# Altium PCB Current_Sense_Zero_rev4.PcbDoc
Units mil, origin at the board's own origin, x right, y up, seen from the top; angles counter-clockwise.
Board outline 2450 x 1350 mil, 2 copper layers (Top Layer, Bottom Layer); 28 components, 9 nets, 61 pads, 43 vias.
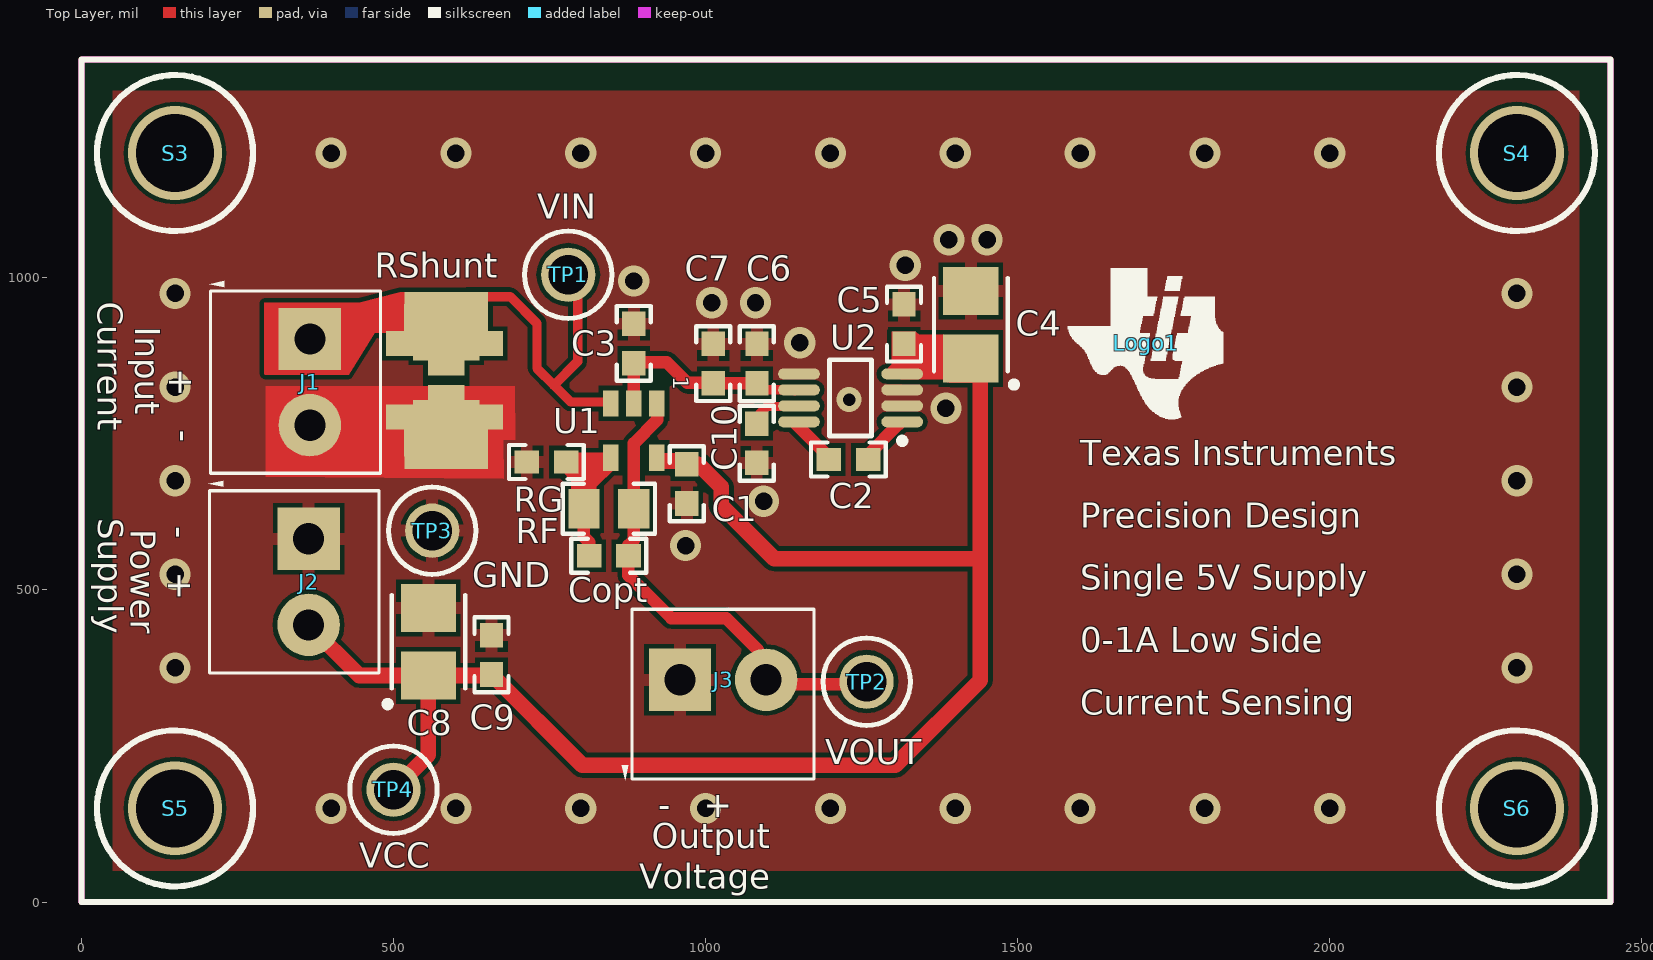
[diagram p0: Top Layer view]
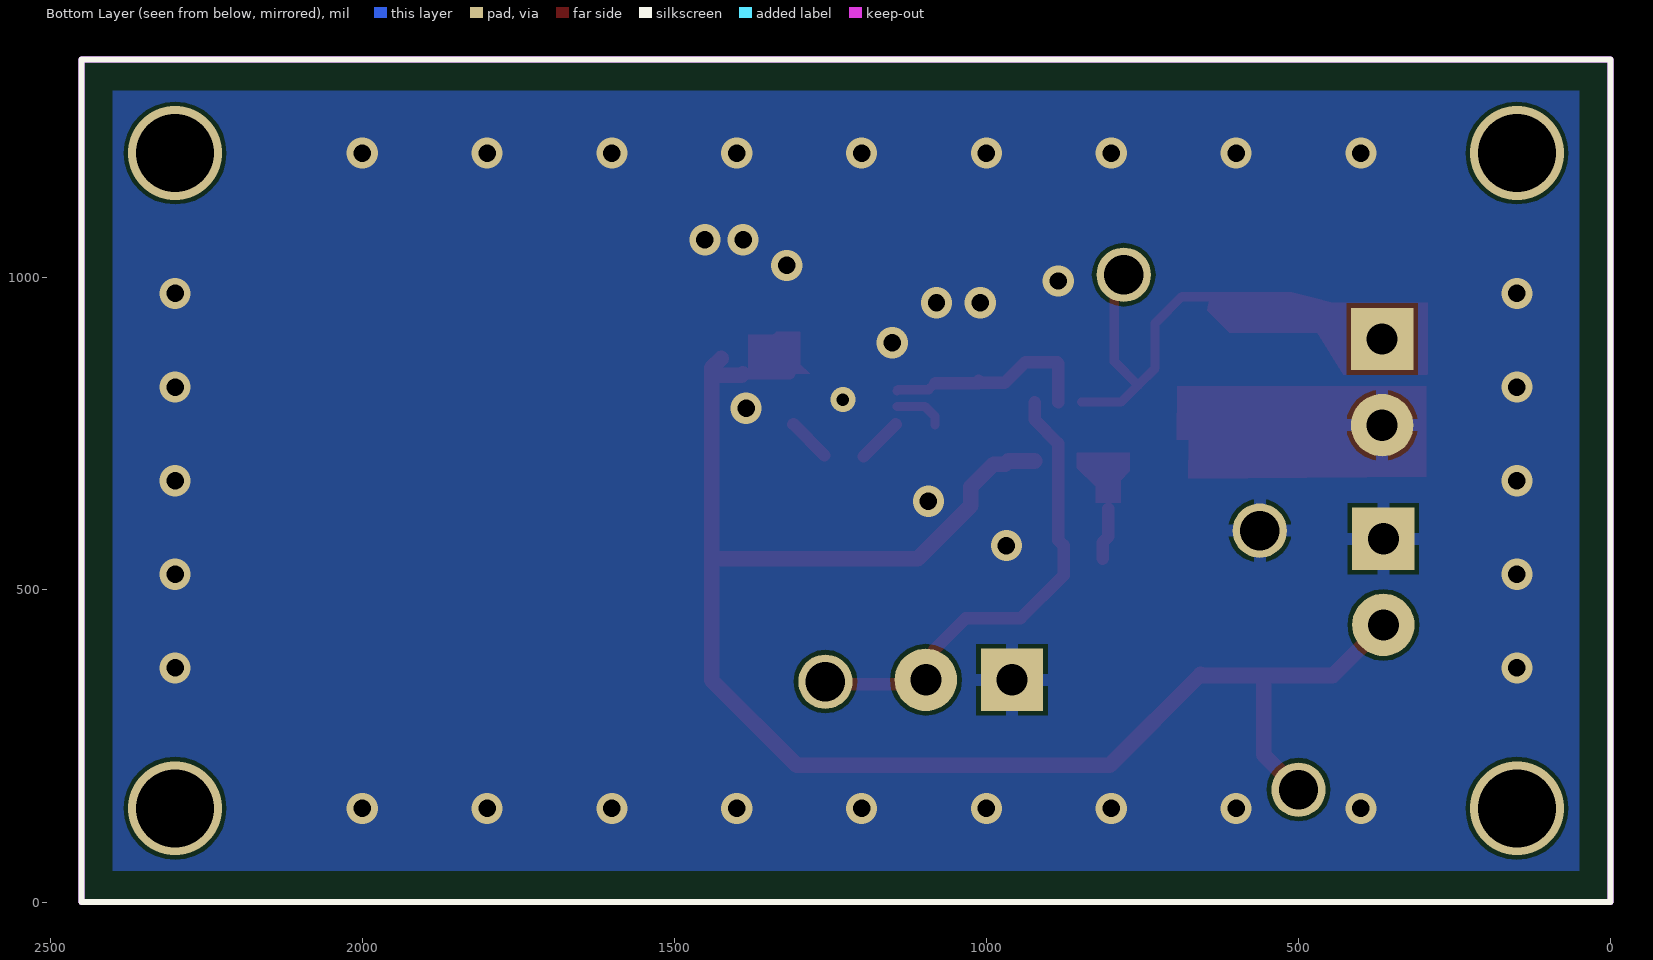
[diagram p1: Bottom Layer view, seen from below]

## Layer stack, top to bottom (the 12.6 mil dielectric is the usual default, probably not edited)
Top Layer: signal copper 1.4
Dielectric: core 12.6, FR-4, Dk 4.8
Bottom Layer: signal copper 1.4

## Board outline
0,0 0,1350 2450,1350 2450,0 0,0

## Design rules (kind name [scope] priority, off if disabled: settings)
AssemblyTestPointUsage [All] p1 off:
AssemblyTestpoint [All] p1 off: testpointundercomponent=TRUE minsize=40 maxsize=100 preferedsize=60 minholesize=0 maxholesize=40 preferedholesize=32 testpointgrid=1 usegrid=TRUE gridtolerance=0.01 allowsidetop=TRUE allowsidebottom=TRUE
Clearance [All] p1: gap=7
ComponentClearance [All] p1 off: gap=10 collisioncheckmode=3 verticalgap=10 showdistances=FALSE
DiffPairsRouting [All] p1 off: maxlimit=10 minlimit=10 mostfreqgap=10 maxuncoupledlength=500
FabricationTestPointUsage TestPointUsage [All] p1 off: valid=0 allowmultiple=FALSE
FabricationTestpoint Testpoint [All] p1 off: side=3 testpointundercomponent=TRUE minsize=40 maxsize=100 preferedsize=60 minholesize=0 maxholesize=40 preferedholesize=32 testpointgrid=1 allowsidetop=TRUE allowsidebottom=TRUE usegrid=TRUE gridtolerance=0.01
FanoutControl Fanout_BGA [IsBGA] p1 off: bgadir=Out bgaviamode=Centered fanoutstyle=Auto fanoutdirection=Alternating viagrid=1 // Fanout_BGA (Default Rule)
FanoutControl Fanout_LCC [IsLCC] p2 off: bgadir=Out bgaviamode=Centered fanoutstyle=Auto fanoutdirection=Alternating viagrid=1 // Fanout_LCC (Default Rule)
FanoutControl Fanout_SOIC [IsSOIC] p3 off: bgadir=Out bgaviamode=Centered fanoutstyle=Auto fanoutdirection=Alternating viagrid=1 // Fanout_SOIC (Default Rule)
FanoutControl Fanout_Small [(CompPinCount < 5)] p4 off: bgadir=Out bgaviamode=Centered fanoutstyle=Auto fanoutdirection=OutThenIn viagrid=1 // Fanout_Small (Default Rule)
FanoutControl Fanout_Default [All] p5 off: bgadir=Out bgaviamode=Centered fanoutstyle=Auto fanoutdirection=Alternating viagrid=1 // Fanout_Default (Default Rule)
Height [All] p1 off: minheight=0 maxheight=1000 prefheight=500
HoleSize [All] p1: absolutevalues=TRUE maxlimit=400 minlimit=15 maxpercent=80.000 minpercent=20.000
HoleToHoleClearance [All] p1: gap=8 allowstackedmicrovias=TRUE
LayerPairs [All] p1 off: enforce=FALSE
MinimumSolderMaskSliver [All] p1: minsoldermaskwidth=4
PlaneConnect [All] p1: planeconnectstyle=Relief reliefexpansion=20 reliefentries=4 reliefconductorwidth=15 reliefairgap=8
PolygonConnect PolygonConnect_1 [IsVia] p1: connectstyle=Direct reliefconductorwidth=15 reliefentries=4 polygonreliefangle="90 Angle" airgapwidth=7
PolygonConnect [(InComponent('U2') AND InNet('GND'))] p2: connectstyle=Direct reliefconductorwidth=10 reliefentries=4 polygonreliefangle="90 Angle" airgapwidth=10
PolygonConnect PolygonConnect_2 [InNet('GND')] p3: connectstyle=Relief reliefconductorwidth=20 reliefentries=4 polygonreliefangle="90 Angle" airgapwidth=7
RoutingVias [All] p1: holewidth=15 width=25 viastyle="Through Hole" minholewidth=15 minwidth=25 maxholewidth=400 maxwidth=500
SilkToSilkClearance [All] p1: silktosilkclearance=5
SilkscreenOverComponentPads [All] p1: minsilkscreentomaskgap=5
SolderMaskExpansion [All] p1: expansion=2
Width [All] p1: maxlimit=100 minlimit=6 preferedwidth=10
9 further rules are at their usual default settings.

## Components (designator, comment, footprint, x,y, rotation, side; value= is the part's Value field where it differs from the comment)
C1 "0603YC104JAT2A" 0603 970,670 r270 top
C2 "C1608X5R1C475M080AC" 0603 1229,709 r0 top
C3 "0603YC104JAT2A" 0603 885,895 r90 top
C4 "TPSB106M020R1000" 3528-21 1425,925 r90 top
C5 "0603YC104JAT2A" 0603 1318,926 r90 top
C6 "0603YC104JAT2A" 0603 1082.32,862.8 r90 top
C7 "CL10A226MP8NUNE" 0603 1012.32,862.8 r90 top
C8 "TPSB106M020R1000" 3528-21 556,417 r90 top
C9 "0603YC104JAT2A" 0603 657,396 r90 top
C10 "CL10A226MP8NUNE" 0603 1082,735 r90 top
Copt "0603YC104JAT2A" 0603 845,555 r180 top
J1 "Input Current" TERM_BLK_ED555-2DS 366,902 r270 top
J2 "Power" TERM_BLK_ED555-2DS 364,582 r270 top
J3 "Output Voltage" TERM_BLK_ED555-2DS 959,356 r0 top
Logo1 "Texas Instruments" TI_Symbol_Overlay_Medium 1705,895 r0 top
RF "RG2012N-364-W-T1" 0805_HV 845,630 r0 top
RG "RG1608N-752-W-T1" 0603 745,705 r0 top
RShunt "Y1487-.1-ND" "MULTI-PAD 0805-2512" 585,835 r90 top
S3 "Standoff" "STANDOFF HEX 4-40THR ALUM 1\"L" 150,1200 r0 top
S4 "Standoff" "STANDOFF HEX 4-40THR ALUM 1\"L" 2300,1200 r0 top
S5 "Standoff" "STANDOFF HEX 4-40THR ALUM 1\"L" 150,150 r0 top
S6 "Standoff" "STANDOFF HEX 4-40THR ALUM 1\"L" 2300,150 r0 top
TP1 "VIN" Keystone5009 780,1005 r90 top
TP2 "VOUT" Keystone5009 1258,353 r90 top
TP3 "GND" Keystone5006 562,595 r0 top
TP4 "VCC" Keystone5005 500,180 r90 top
U1 "OPA320AIDBVR" SOT23-5P 885,753.78 r270 top
U2 "LM7705MM" MUA08A_N 1232.32,807.8 r180 top

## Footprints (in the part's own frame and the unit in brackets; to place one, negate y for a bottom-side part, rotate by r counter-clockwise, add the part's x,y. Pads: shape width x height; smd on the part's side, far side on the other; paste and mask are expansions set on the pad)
0603 [mm] "0603 from SM-752 data"
  rect 1x0.95 smd: 1(-0.8,0) 2(0.8,0)
  silkscreen extent -1.52,-0.69 1.52,0.69, body extent -0.87,-0.47 0.87,0.47, height 0.85
0805_HV [mil] "0805 with 30mil clearance between pads"
  rect 50x63 smd: 1(-40,0) 2(40,0)
  silkscreen extent -74,-40 74,40, body extent -43,-29 43,29, height 43
3528-21 [mm] "Medium Density IPC, based on SM-782 section 8.4"
  rect 1.95x2.25 smd: 1(-1.375,0) 2(1.375,0)
  silkscreen extent -2.56,-1.88 1.9,1.5, body extent -1.85,-1.5 1.85,1.5, height 2.1
Keystone5005 [mil] "Keystone Compact loops"
  round 87 hole 63: 1(0,0)
  silkscreen extent -70,-70 70,70, body extent -63,-63 62,63, height 225
Keystone5006 [mil] "Keystone Compact loops"
  round 87 hole 63: 1(0,0)
  silkscreen extent -70,-70 70,70, body extent -63,-63 62,63, height 225
Keystone5009 [mil] "Keystone Compact loops"
  round 87 hole 63: 1(0,0)
  silkscreen extent -70,-70 70,70, body extent -63,-63 62,63, height 225
MUA08A_N [mm] "TSOP, 8-Leads, Body 3x3mm, Pitch 0.65mm, IPC Medium Density"
  oval 1.7x0.45 smd: 1(-2.1,0.975) 2(-2.1,0.325) 3(-2.1,-0.325) 4(-2.1,-0.975) 5(2.1,-0.975) 6(2.1,-0.325) 7(2.1,0.325) 8(2.1,0.975)
  silkscreen extent -2.22,-1.55 0.85,1.87, body extent -1.6,-1.6 1.6,1.6, height 1.09
"MULTI-PAD 0805-2512" [mm] "Fits SMT passives (0805/1206/1210/1218/2010/2512)"
  rect 1.3x3.4 smd: 1(-2.933,0.007) 2(2.967,0.007)
  rect 1.6x3.4 smd: 1(-2.277,0.022) 2(2.323,0.022)
  rect 1.016x4.75 smd: 1(-1.471,0.084) 2(1.526,0.084)
  rect 1.3x2.7 smd: 1(-1.422,0.015) 2(1.478,0.015)
  rect 1.3x1.85 smd: 1(-1.421,0.011) 2(1.479,0.011)
  rect 1.3x1.5 smd: 1(-0.827,0.011) 2(0.873,0.011)
  body extent -3.21,-2.29 3.24,2.46, height 1.66
SOT23-5P [mil]
  rect 42x25 smd: 1(-45,37) 2(-45,0) 3(-45,-37) 4(42,-37) 5(42,37)
"STANDOFF HEX 4-40THR ALUM 1\"L" [mil] "STANDOFF HEX 4-40THR ALUM 1\"L"
  silkscreen extent -125,-125 125,125
TERM_BLK_ED555-2DS [mil]
  rect 100x100 hole 50: 1(0,0)
  round 100 hole 50: 2(138,0)
  silkscreen extent -93,-161 215,113, body extent -69,-150 207,106, height 323
TI_Symbol_Overlay_Medium [mil]
  silkscreen extent -124,-122 124,120

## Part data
C1 C3 C5 C6 C9 Copt: "CAP, CERM, 0.1uF, 16V, +/-5%, X7R, 0603"
C2: library part 0603ZD475KAT2A, "CAP, CERM, 4.7uF, 10V, +/-10%, X5R, 0603"
C4 C8: "CAP, TANT, 10uF, 20V, +/-20%, 1 ohm, 3528-21 SMD"
C7 C10: "CAP, CERM, 22uF, 10V, +/-20%, X5R, 0603"
J1 J2 J3: library part ED555/2DS, "Terminal Block, 6A, 3.5mm Pitch, 2-Pos, TH"
Logo1: library part TI_Logo, "Texas Instrument Corporate Signature"
RF: library part RG2012P-364-B-T5, "RES, 360k ohm, 0.1%, 0.125W, 0805"
RG: library part RC0603JR-077K5L, "RES, 7.5k ohm, 5%, 0.1W, 0603"
RShunt: library part "Multi-Pad Resistor", "0805-2512 SMT Passive Pad for Shunt Resistor"
S3 S4 S5 S6: library part "Standoff, 1\", 4-40, Alum, F-F", "STANDOFF HEX 4-40THR ALUM 1\"L"
TP1 TP2: library part 5009, "Test Point, TH, Compact, Yellow"
TP3: library part 5006, "Test Point, TH, Compact, Black"
TP4: library part 5005, "Test Point, TH, Compact, Red"
U1: "IC, Precision, 20MHz, 0.9pA, Low-Noise, RRIO, CMOS Op-Amp"
U2: "Low Noise Negative Bias Generator, 8-pin Mini SOIC"

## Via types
v1: diameter 50, hole 28, Top Layer to Bottom Layer, 38 vias
v2: diameter 150, hole 125, Top Layer to Bottom Layer, 3 vias
v3: diameter 40, hole 20, Top Layer to Bottom Layer, 1 vias
v4: diameter 150, hole 125, Top Layer to Bottom Layer, tented top, 1 vias

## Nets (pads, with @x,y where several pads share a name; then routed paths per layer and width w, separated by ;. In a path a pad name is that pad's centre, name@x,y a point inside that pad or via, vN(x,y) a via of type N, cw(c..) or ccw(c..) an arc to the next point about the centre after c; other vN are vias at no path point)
GND: C1.2 C3.2 C4.2 C5.2 C6.2 C7.2 C8.2 C9.2 C10.1 J1.2 J2.1 J3.1 RG.1 RShunt.1 TP3.1 U2.2 U2.3 U2.5
  other v1: 400,150 600,150 800,150 1000,150 1200,150 1400,150 1600,150 1800,150 2000,150 150,375 2300,375 150,525 2300,525 968,571 1093,642 150,675 2300,675 1385,791 150,825 2300,825 1151,896 1010,960 1080,960 150,975 2300,975 885,995 1320,1020 1390,1061 1451,1061 400,1200 600,1200 800,1200 1000,1200 1200,1200 1400,1200 1600,1200 1800,1200 2000,1200
  other v3: 1230,805
NetC2_1: C2.1 U2.8 | length 72.5
  Top Layer w20: U2.8@1145.24,765.71 C2.1@1196.48,714.48
NetC2_2: C2.2 U2.1 | length 70.1
  Top Layer w20: C2.2@1259.88,716.12 U2.1@1309.44,765.68
NetC3_1: C3.1 C6.1 C7.1 U1.2 U2.6 | length 338.6
  Top Layer w15: C6.1 1092.62,821 1141.57,821 U2.6@1143.14,819.43
  Top Layer w20: U1.2@885,801.02 C3.1 ; C3.1@886.5,865 937.6,865 970.6,832 1009,832 C7.1@1012,835 ; C7.1 C6.1
NetC10_2: C10.2 U2.7 | length 81
  Top Layer w15: C10.2@1082.32,764.29 1082.32,777.8 1098.36,793.83 U2.7@1143.14,793.83
NetCopt_1: Copt.1 J3.2 RF.2 TP2.1 U1.1 | length 766.5
  Top Layer w20: U1.1@922.4,801.02 922.4,772.4 885,735 RF.2 885,580 876.5,571.5 Copt.1 876.5,523.5 945,455 1033,455 1084,404 J3.2@1084,342 ; J3.2@1088,349 TP2.1@1239,349
NetCopt_2: Copt.2 RF.1 RG.2 U1.4 | length 83.5
  Top Layer w20: RF.1 805,585 813.5,576.5 Copt.2@813.5,550
NetJ1_1: J1.1 RShunt.2 TP1.1 U1.3 | length 566.8
  Top Layer w15: RShunt.2@616.89,970 687,970 730,927 730,855 756.99,828.01 ; TP1.1@795,1015 795,866.02 756.99,828.01 ; U1.3@847.6,801.02 783.98,801.02 756.99,828.01
  Top Layer w25: TP1.1@780,1030 TP1.1@795,1015
VCC: C1.1 C4.1 C5.1 C8.1 C9.1 J2.2 TP4.1 U1.5 U2.4 | length 2723.1
  Top Layer w18: C5.1@1320,893.5 1315,888.5 U2.4 C4.1@1390.43,846.18
  Top Layer w25: J2.2 445.13,362.87 C8.1 ; TP4.1 556,236 C8.1 ; U1.5@922.4,706.54 C1.1@965,706.54 ; C1.1 988.5,701.5 1025,665 1025,635 1110,550 1440,550 ; C4.1@1390.43,846.18 1392.32,844.29 C4.1@1440,844.29 ; C4.1 1440,855.87 C4.1@1440,844.29 ; C8.1 655.36,362.87 C9.1 802.5,219 1304,219 1440,355 1440,550 ; 1440,550 C4.1@1440,844.29
copper on no net: | length 15200
  Top Layer w10: 0,0 2450,0 2450,1350 0,1350 0,0
  Bottom Layer w10: 0,0 2450,0 2450,1350 0,1350 0,0
  other v2: 150,150 2300,150 2300,1200
  other v4: 150,1200

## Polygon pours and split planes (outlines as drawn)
GND on Top Layer "Top Layer-No Net" (solid, remove dead copper, pour order 6): 50,1300 2400,1300 2400,50 50,50
GND on Bottom Layer "Bottom Layer-No Net" (solid, remove dead copper, pour order 4): 50,1300 2400,1300 2400,50 50,50

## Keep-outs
Keep-Out Layer:
  the board outline again, w10

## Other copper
Top Layer:
  region net GND: 295,826 694,826 695,741 676,740 677,678 295,681
  region net NetJ1_1: 293,960 444,960 510,977 641,977 646,949 647,948 611,912 470,912 428,845 294,845 293,846
  region net NetCopt_2: 770,720 770,690 785,675 785,640 825,640 825,665 855,695 855,720
  region net VCC: 1282,846 1298,862 1298,914 1337,914 1342,909 1382,909 1382,850 1388,844

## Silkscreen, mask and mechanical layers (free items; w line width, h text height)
Top Overlay:
  the board outline again, w10
  text "Current" at 26,962 h40 r270
  text "Input" at 86,922 h40 r270
  text "-   +" at 176,737 h40 r90
  text "Supply" at 27,615 h40 r270
  text "-   +" at 139,602 h40 r270
  text "Precision Design" at 1600,600 h40
  text "Single 5V Supply" at 1600,500 h40
  text "0-1A Low Side" at 1600,400 h40
  text "Current Sensing" at 1600,300 h40
  text "-   +" at 924,136 h40
  text "Output" at 914,86 h40
  text "Voltage" at 894,21 h40
Bottom Overlay:
  the board outline again, w10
